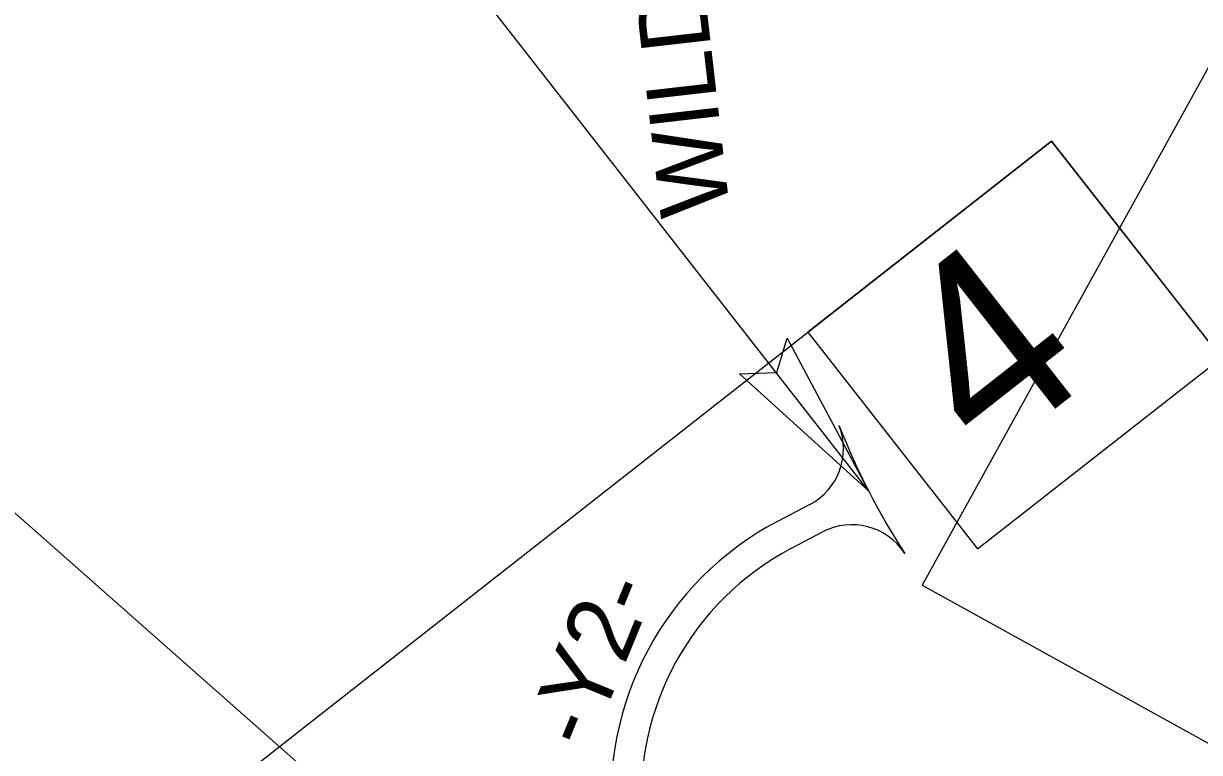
# Model space of a CAD drawing. Extents: x 2170913 to 2188101, y 74009 to 87693.
# Drawn here: x 2175486 to 2176418, y 77496 to 78074 of the extents above; entities that cross this region are included whole.
import ezdxf

# ---------------------------------------------------------------- set-up
doc = ezdxf.new("R2010")
doc.units = 0
for name, color, linetype in [('Exist Property Iron Pin CELL', 7, 'Continuous'), ('Exist Right of Way Monument CELL', 7, 'Continuous'), ('Exist Structure Minor Storm Sewer Manhole CELL', 7, 'Continuous'), ('Exist Utilities Water Fire Hydrant CELL', 7, 'Continuous')]:
    doc.layers.add(name, color=color, linetype=linetype)

msp = doc.modelspace()

# ---------------------------------------------------------------- linework, layer by layer
at = {"layer": 'Exist Property Iron Pin CELL'}
for p, q in [((2176155.47, 77703.36), (2175504.92, 78536.66)), ((2175848.59, 77359.41), (2175465.59, 77697.52))]:
    msp.add_line(p, q, dxfattribs=at)
at = {"layer": 'Exist Right of Way Monument CELL'}
for points in [[(2177117.21, 77120.7), (2177842.75, 78433.56), (2176923.74, 78941.44), (2176198.21, 77628.58)], [(2175120.11, 77054.97), (2176300.66, 77980.34), (2176948.42, 77153.96), (2175767.87, 76228.59)], [(2176300.66, 77980.34), (2176107.4, 77828.85), (2176241.99, 77657.15), (2176435.25, 77808.63)]]:
    msp.add_lwpolyline(points, close=True, dxfattribs=at)
at = {"layer": 'Exist Structure Minor Storm Sewer Manhole CELL'}
msp.add_lwpolyline([(2176091.08, 77824.27), (2176155.47, 77703.36), (2176053.29, 77795.89), (2176082.83, 77796.98)], close=True, dxfattribs=at)
at = {"layer": 'Exist Utilities Water Fire Hydrant CELL'}
for p, q in [((2176109.09, 77692.5), (2176083.35, 77678.95)), ((2176094.53, 77657.72), (2176119.08, 77670.64))]:
    msp.add_line(p, q, dxfattribs=at)
for centre, radius, start, end in [((2176085.8, 77736.74), 50, 297.76258, 21.18009), ((2176642.44, 77952.43), 546.97, 201.18009, 213.10348), ((2176198.41, 77460.39), 247, 117.76258, 185.97894), ((2176142.37, 77626.39), 50, 33.10348, 117.76258), ((2176198.41, 77460.39), 223, 117.76258, 184.66686)]:
    msp.add_arc(centre, radius, start, end, dxfattribs=at)

# ---------------------------------------------------------------- texts
at = {"layer": 'Exist Property Iron Pin CELL'}
for s, height, rotation, p in [('WILDWOOD ST NW', 55.0465, 96.53875, (2176045.84, 77924.33)), ('-Y2-', 55.047, 67.75635, (2175934.11, 77496.35))]:
    msp.add_text(s, height=height, rotation=rotation, dxfattribs=at).set_placement(p)
at = {"layer": 'Exist Right of Way Monument CELL'}
msp.add_text('4', height=147.62, rotation=38.09105, dxfattribs=at).set_placement((2176249.6, 77726))

doc.saveas('drawing.dxf')
